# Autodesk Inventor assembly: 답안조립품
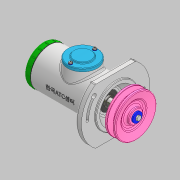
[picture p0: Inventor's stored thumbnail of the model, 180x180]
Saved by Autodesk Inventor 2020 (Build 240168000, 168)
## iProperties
Created: 2022-05
Part Number: 답안조립품
Document SubType Name: Assembly
Designer: User
Author: User
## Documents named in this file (22)
- C:\Users\User\Desktop\720506V1010\답안조립품.iam
- C:\Users\User\Desktop\720506V1010\본체.ipt
- C:\Users\User\Desktop\720506V1010\V-벨트풀리.ipt
- C:\Users\User\Desktop\720506V1010\개스킷.ipt
- C:\Users\User\Desktop\720506V1010\너트 M10.ipt
- C:\Users\User\Desktop\720506V1010\멈춤나사 M3.ipt
- C:\Users\User\Desktop\720506V1010\멈춤링 15 x 1.ipt
- C:\Users\User\Desktop\720506V1010\멈춤링 35 x 1.6.ipt
- C:\Users\User\Desktop\720506V1010\베어링 6202.ipt
- C:\Users\User\Desktop\720506V1010\볼트 M4 x 10.ipt
- C:\Users\User\Desktop\720506V1010\부시1.ipt
- C:\Users\User\Desktop\720506V1010\부시2.ipt
- C:\Users\User\Desktop\720506V1010\사이드 커버.ipt
- 사이드 커버.ipt
- C:\Users\User\Desktop\720506V1010\십자볼트 M3 x 10.ipt
- C:\Users\User\Desktop\720506V1010\오일 실 15 x 30 x 7.ipt
- C:\Users\User\Desktop\720506V1010\와셔 3 x 6.ipt
- C:\Users\User\Desktop\720506V1010\와셔 4 x 16.ipt
- C:\Users\User\Desktop\720506V1010\와셔 10 x 21.ipt
- C:\Users\User\Desktop\720506V1010\축.ipt
- C:\Users\User\Desktop\720506V1010\키 4 x 4.ipt
- C:\Users\User\Desktop\720506V1010\탑 커버.ipt
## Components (3 placed, 3 different names)
1. V-벨트풀리:1
2. 개스킷:1 — 각도:16
3. ISO 4017 M4 x 10:1 — 각도:12
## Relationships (2: Angle 2)
- 각도:12 [Angle]: ISO 4017 M4 x 10:1
- 각도:16 [Angle]: 개스킷:1
